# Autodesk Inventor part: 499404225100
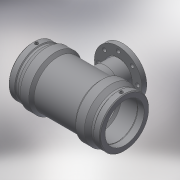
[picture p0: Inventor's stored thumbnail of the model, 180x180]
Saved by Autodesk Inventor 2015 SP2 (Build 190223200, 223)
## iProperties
Created: 2017-06
Part Number: 499404225100
Material: Generic
Description: PLASSON FLANGED TEE 225x100x225
Document SubType Name: Modeling
Designer: KIM
Mass: 57.3761 g
Surface Area: 241.06 cm^2
Volume: 57.3761 cm^3
Density: 1 g/cm^3
Appearance: Default
Author: KIM
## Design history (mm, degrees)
derived "499404.ipt"
feature "Solid1::499404.ipt"
tag "TaggingFeature1"
body "Solid1"
other parameters: "d13" = 494, "d14" = 17.6296, "d17" = 202.5, "d18" = 225, "d19" = 3.52592, "d20" = 168 deg, "d22" = 272.49, "d23" = 293, "d24" = 264.3153, "d25" = 135 deg, "d26" = 345.8, "d27" = 135 deg, "d35" = 15, "d39" = 5 deg, "d45" = 4, "d46" = 14, "d47" = 0, "d55" = 263.7, "d56" = 293, "d57" = 172.9, "d58" = 135 deg, "d59" = 122, "d60" = 122, "d61" = 135 deg, "d72" = 224.77, "d73" = 112.385, "d87" = 158, "d90" = 125, "d91" = 15 deg, "d93" = 22, "d95" = 4.74, "d97" = 18, "d100" = 0, "d102" = 360 deg, "d105" = 0, "d107" = 0, "d108" = 3, "d109" = 0, "d110" = 36.6, "d111" = 12.2, "d_" = 225, "L_" = 494, "L_1" = 122, "D_" = 293, "d_2" = 12, "t_" = 22, "d_1" = 158, "s_" = 18
